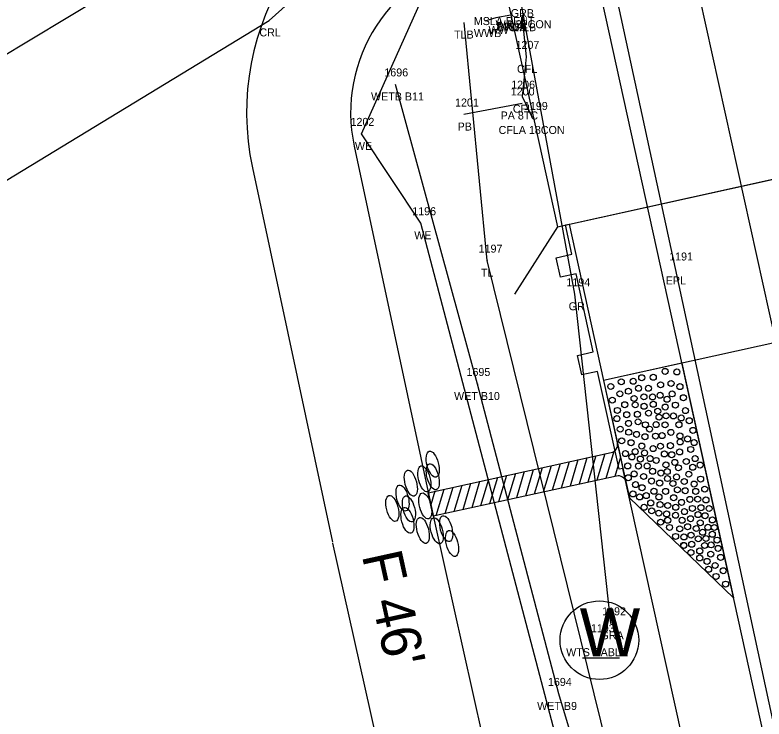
# Model space of a CAD drawing. Extents: x 2521558 to 2524785, y 882711 to 887632.
# Drawn here: x 2523713 to 2523806.5, y 884989.6 to 885077.6 of the extents above; entities that cross this region are included whole.
import ezdxf

# ---------------------------------------------------------------- set-up
doc = ezdxf.new("R2010")
doc.units = 0
for name, color, linetype in [('RD_EV_JW', 7, 'Continuous'), ('RD_EX_BldgApp_txCode', 7, 'Continuous'), ('RD_EX_Bridge', 7, 'Continuous'), ('RD_EX_Bridge_txCode', 7, 'Continuous'), ('RD_EX_Conc', 7, 'Continuous'), ('RD_EX_Conc_txCode', 7, 'Continuous'), ('RD_EX_DR_Pipe', 7, 'Continuous'), ('RD_EX_DR_Pipe_txCode', 7, 'Continuous'), ('RD_EX_GuardRail', 7, 'Continuous'), ('RD_EX_GuardRail_txCode', 7, 'Continuous'), ('RD_EX_H2O', 7, 'Continuous'), ('RD_EX_H2O_txCode', 7, 'Continuous'), ('RD_EX_H2O_WetLd_txCode', 7, 'Continuous'), ('RD_EX_Misc_txCode', 7, 'Continuous'), ('RD_EX_Road', 7, 'Continuous'), ('RD_EX_Road_txCode', 7, 'Continuous'), ('RD_EX_UT', 7, 'Continuous'), ('RD_EX_UT_txCode', 7, 'Continuous'), ('RD_EX_VEG', 7, 'Continuous'), ('RD_EX_VEG_txCode', 7, 'Continuous'), ('RD_HC_Cl', 7, 'Continuous'), ('RD_PD_Bridge', 7, 'Continuous'), ('RD_PD_CstnLmt', 7, 'Continuous'), ('RD_PD_DR_ErosCtrl', 7, 'Continuous'), ('RD_PD_Final_TrvlWay', 7, 'Continuous'), ('RD_PD_GR', 7, 'Continuous'), ('RD_PD_PaveShd', 7, 'Continuous'), ('RD_SMD_Locator', 7, 'Continuous')]:
    doc.layers.add(name, color=color, linetype=linetype)

# ---------------------------------------------------------------- blocks, each defined once
blk = doc.blocks.new('TBC1')
at = {"layer": 'RD_PD_GR'}
blk.add_lwpolyline([(12.5, 2.5), (15, 2.5), (15, 0.492), (25, 0.492), (25, 2.5), (27.5, 2.5), (27.5, 0.492), (31.25, 0.492), (31.25, 0), (0, 0), (0, 0.492), (12.5, 0.492)], close=True, dxfattribs=at)

msp = doc.modelspace()

# ---------------------------------------------------------------- linework, layer by layer
at = {"layer": 'RD_EV_JW'}
msp.add_lwpolyline([(2523827.748, 884469.643), (2523867.429, 884517.673), (2523885.95, 884534.838), (2523882.771, 884582.718), (2523847.739, 884736.424), (2523822.93, 884833.786), (2523804.257, 884914.891), (2523780.91, 884992.763), (2523770.735, 885031.476), (2523760.496, 885068.896)], dxfattribs=at)
at = {"layer": 'RD_EX_Bridge'}
msp.add_lwpolyline([(2523774.897, 885077.54), (2523773.018, 885077.212), (2523771.668, 885076.8)], dxfattribs=at)
at = {"layer": 'RD_EX_Conc'}
msp.add_lwpolyline([(2523777.605, 885064.707), (2523776.362, 885067.363), (2523776.876, 885072.337), (2523776.323, 885077.543)], dxfattribs=at)
at = {"layer": 'RD_EX_DR_Pipe'}
msp.add_line((2523776.322, 885066.515), (2523769.037, 885065.137), dxfattribs=at)
at = {"layer": 'RD_EX_GuardRail'}
msp.add_lwpolyline([(2523787.377, 885001.584), (2523782.908, 885042.685), (2523776.151, 885079.302)], dxfattribs=at)
at = {"layer": 'RD_EX_H2O'}
for points in [[(2523582.816, 884766.342), (2523598.112, 884856.984), (2523627.586, 884901.753), (2523623.762, 884928.278), (2523586.58, 884955.428), (2523600.942, 884974.118), (2523633.055, 884997.681), (2523679.166, 885037.048), (2523744.717, 885076.895), (2523769.376, 885098.995), (2523825.47, 885108.66), (2523825.47, 885108.66), (2523845.237, 885110.828), (2523890.252, 885154.934), (2523858.435, 885178.041), (2523850.814, 885196.928), (2523892.509, 885249.744), (2523936.89, 885290.086), (2523980.857, 885285.467), (2524009.058, 885269.77), (2524037.386, 885280.087)], [(2523792.732, 884941.121), (2523763.674, 885051.555), (2523756.264, 885062.719), (2523770.471, 885094.548), (2523817.567, 885105.706), (2523827.825, 885105.996)]]:
    msp.add_lwpolyline(points, dxfattribs=at)
at = {"layer": 'RD_EX_Road'}
for p, q in [((2523795.465, 885045.906), (2523788.047, 885080.306)), ((2523816.996, 884946.299), (2523795.465, 885045.906))]:
    msp.add_line(p, q, dxfattribs=at)
at = {"layer": 'RD_EX_UT'}
msp.add_line((2523783.84, 884997.269), (2523788.469, 884997.269), dxfattribs=at)
msp.add_circle((2523785.968, 884999.477), 4.908, dxfattribs=at)
at = {"layer": 'RD_EX_VEG'}
msp.add_lwpolyline([(2523800.231, 884418.22), (2523892.245, 884498.974), (2523844.575, 884752.813), (2523771.945, 885046.883), (2523769.056, 885076.621)], dxfattribs=at)
at = {"layer": 'RD_HC_Cl'}
for p, q in [((2523641.165, 885794.201), (2524197.759, 883266.557)), ((2523672.044, 885048.634), (2523837.18, 885148.323))]:
    msp.add_line(p, q, dxfattribs=at)
at = {"layer": 'RD_PD_Bridge'}
for p, q in [((2523780.729, 885051.128), (2523826.629, 885061.235)), ((2523782.194, 885051.45), (2523786.495, 885031.918)), ((2523780.729, 885051.128), (2523775.344, 885042.702)), ((2523829.465, 885041.381), (2523786.495, 885031.918))]:
    msp.add_line(p, q, dxfattribs=at)
for points in [[(2523752.772, 885178.086), (2523780.729, 885051.128)], [(2523780.729, 885051.128), (2523826.629, 885061.235)]]:
    msp.add_lwpolyline(points, dxfattribs=at)
at = {"layer": 'RD_PD_CstnLmt'}
for p, q in [((2523755.336, 885061.182), (2523765.326, 885014.455)), ((2523765.326, 885014.455), (2523787.173, 884916.87))]:
    msp.add_line(p, q, dxfattribs=at)
msp.add_arc((2523774.894, 885065.364), 20, 102.41848, 192.06773, dxfattribs=at)
at = {"layer": 'RD_PD_DR_ErosCtrl'}
for p, q in [((2523742.623, 885058.464), (2523752.613, 885011.737)), ((2523752.64, 885011.615), (2523774.487, 884914.03))]:
    msp.add_line(p, q, dxfattribs=at)
msp.add_arc((2523774.894, 885065.364), 33, 102.41848, 192.06773, dxfattribs=at)
at = {"layer": 'RD_PD_Final_TrvlWay'}
msp.add_line((2523718.306, 885388.085), (2523992.495, 884142.916), dxfattribs=at)
at = {"layer": 'RD_PD_GR'}
msp.add_line((2523896.44, 884532.63), (2523788.914, 885020.932), dxfattribs=at)
at = {"layer": 'RD_PD_PaveShd'}
for p, q in [((2523796.261, 885034.069), (2523786.495, 885031.918)), ((2523796.261, 885034.069), (2523802.712, 885004.771)), ((2523786.495, 885031.918), (2523788.43, 885023.129)), ((2523764.591, 885017.892), (2523787.453, 885022.914)), ((2523785.523, 885022.49), (2523784.539, 885019.203)), ((2523785.523, 885022.49), (2523784.539, 885019.203)), ((2523786.64, 885022.736), (2523785.656, 885019.448)), ((2523786.64, 885022.736), (2523785.656, 885019.448)), ((2523787.777, 885023.049), (2523786.773, 885019.693)), ((2523788.43, 885023.129), (2523789.076, 885020.199)), ((2523781.053, 885021.509), (2523780.069, 885018.221)), ((2523781.053, 885021.509), (2523780.069, 885018.221)), ((2523782.171, 885021.754), (2523781.187, 885018.466)), ((2523782.171, 885021.754), (2523781.187, 885018.466)), ((2523783.288, 885021.999), (2523782.304, 885018.712)), ((2523784.405, 885022.245), (2523783.421, 885018.957)), ((2523784.405, 885022.245), (2523783.421, 885018.957)), ((2523788.606, 885022.33), (2523787.89, 885019.939)), ((2523777.702, 885020.772), (2523776.718, 885017.485)), ((2523777.702, 885020.772), (2523776.718, 885017.485)), ((2523778.819, 885021.018), (2523777.835, 885017.73)), ((2523778.819, 885021.018), (2523777.835, 885017.73)), ((2523779.936, 885021.263), (2523778.952, 885017.975)), ((2523779.936, 885021.263), (2523778.952, 885017.975)), ((2523788.099, 885019.985), (2523765.218, 885014.959)), ((2523773.233, 885019.791), (2523772.249, 885016.503)), ((2523773.233, 885019.791), (2523772.37, 885016.908)), ((2523774.35, 885020.036), (2523773.366, 885016.748)), ((2523774.35, 885020.036), (2523773.366, 885016.748)), ((2523775.467, 885020.281), (2523774.483, 885016.994)), ((2523775.467, 885020.281), (2523774.483, 885016.994)), ((2523776.584, 885020.527), (2523775.6, 885017.239)), ((2523776.584, 885020.527), (2523775.6, 885017.239)), ((2523789.076, 885020.199), (2523789.721, 885017.269)), ((2523768.763, 885018.809), (2523767.779, 885015.521)), ((2523768.763, 885018.809), (2523767.779, 885015.521)), ((2523769.881, 885019.054), (2523768.897, 885015.767)), ((2523769.881, 885019.054), (2523768.897, 885015.767)), ((2523770.998, 885019.3), (2523770.014, 885016.012)), ((2523770.998, 885019.3), (2523770.014, 885016.012)), ((2523772.115, 885019.545), (2523771.131, 885016.258)), ((2523772.115, 885019.545), (2523771.131, 885016.258)), ((2523765.218, 885014.959), (2523764.591, 885017.892)), ((2523765.412, 885018.073), (2523764.91, 885016.398)), ((2523766.529, 885018.318), (2523765.545, 885015.03)), ((2523766.529, 885018.318), (2523765.666, 885015.436)), ((2523767.646, 885018.564), (2523766.662, 885015.276)), ((2523767.646, 885018.564), (2523766.662, 885015.276)), ((2523802.712, 885004.771), (2523789.721, 885017.269))]:
    msp.add_line(p, q, dxfattribs=at)
for centre in [(2523794.177, 885033.047), (2523794.177, 885033.047), (2523795.645, 885032.98), (2523795.645, 885032.98), (2523788.701, 885031.749), (2523788.701, 885031.749), (2523790.191, 885031.82), (2523790.191, 885031.82), (2523791.255, 885032.267), (2523791.255, 885032.267), (2523792.695, 885032.312), (2523792.695, 885032.312), (2523794.925, 885031.542), (2523794.925, 885031.542), (2523787.391, 885031.169), (2523787.391, 885031.169), (2523787.391, 885031.169), (2523789.59, 885030.574), (2523789.59, 885030.574), (2523790.857, 885030.939), (2523790.857, 885030.939), (2523792.098, 885030.94), (2523792.098, 885030.94), (2523793.614, 885031.376), (2523793.614, 885031.376), (2523796.028, 885031.15), (2523796.028, 885031.15), (2523788.522, 885030.252), (2523788.522, 885030.252), (2523790.297, 885029.666), (2523790.297, 885029.666), (2523791.529, 885029.869), (2523791.529, 885029.869), (2523792.61, 885029.863), (2523792.61, 885029.863), (2523793.554, 885030.07), (2523793.554, 885030.07), (2523794.424, 885029.569), (2523794.424, 885029.569), (2523795.053, 885030.242), (2523795.053, 885030.242), (2523796.459, 885029.76), (2523796.459, 885029.76), (2523787.581, 885029.458), (2523787.581, 885029.458), (2523789.128, 885028.892), (2523789.128, 885028.892), (2523790.445, 885028.871), (2523790.445, 885028.871), (2523791.55, 885028.688), (2523791.55, 885028.688), (2523792.699, 885028.941), (2523792.699, 885028.941), (2523794.188, 885028.599), (2523794.188, 885028.599), (2523795.46, 885028.839), (2523795.46, 885028.839), (2523788.21, 885028.175), (2523788.21, 885028.175), (2523790.717, 885027.693), (2523790.717, 885027.693), (2523792.104, 885027.837), (2523792.104, 885027.837), (2523793.26, 885028.082), (2523796.722, 885028.151), (2523796.722, 885028.151), (2523788.153, 885027.158), (2523788.153, 885027.158), (2523789.378, 885027.639), (2523789.378, 885027.639), (2523790.809, 885026.756), (2523790.809, 885026.756), (2523793.423, 885027.339), (2523793.423, 885027.339), (2523794.299, 885027.497), (2523794.299, 885027.497), (2523795.224, 885027.483), (2523795.224, 885027.483), (2523796.188, 885027.242), (2523796.188, 885027.242), (2523797.198, 885026.893), (2523797.198, 885026.893), (2523788.569, 885025.835), (2523788.569, 885025.835), (2523789.612, 885026.556), (2523789.612, 885026.556), (2523791.71, 885026.383), (2523791.71, 885026.383), (2523792.229, 885025.836), (2523792.229, 885025.836), (2523793.053, 885026.403), (2523793.053, 885026.403), (2523794.168, 885026.372), (2523794.168, 885026.372), (2523795.909, 885026.389), (2523795.909, 885026.389), (2523789.633, 885025.454), (2523789.633, 885025.454), (2523790.607, 885025.184), (2523790.607, 885025.184), (2523791.656, 885024.89), (2523791.656, 885024.89), (2523792.982, 885024.969), (2523792.982, 885024.969), (2523793.808, 885025.033), (2523793.808, 885025.033), (2523794.899, 885025.43), (2523794.899, 885025.43), (2523796.028, 885024.989), (2523796.028, 885024.989), (2523797.661, 885025.679), (2523797.661, 885025.679), (2523788.751, 885024.374), (2523788.751, 885024.374), (2523789.924, 885024.147), (2523789.924, 885024.147), (2523796.051, 885024.238), (2523796.051, 885024.238), (2523796.992, 885024.618), (2523796.992, 885024.618), (2523797.807, 885024.157), (2523790.438, 885023.028), (2523790.438, 885023.028), (2523791.266, 885023.725), (2523791.266, 885023.725), (2523792.68, 885023.406), (2523792.68, 885023.406), (2523793.598, 885023.71), (2523793.598, 885023.71), (2523794.837, 885023.774), (2523794.837, 885023.774), (2523795.989, 885022.995), (2523795.989, 885022.995), (2523797.383, 885023.302), (2523797.383, 885023.302), (2523789.226, 885022.785), (2523789.226, 885022.785), (2523790.029, 885022.359), (2523790.029, 885022.359), (2523791.09, 885022.103), (2523791.09, 885022.103), (2523791.609, 885022.864), (2523791.609, 885022.864), (2523792.304, 885022.154), (2523792.304, 885022.154), (2523794.092, 885022.736), (2523794.092, 885022.736), (2523795.002, 885022.647), (2523795.002, 885022.647), (2523797.929, 885022.157), (2523797.929, 885022.157), (2523789.509, 885021.243), (2523789.509, 885021.243), (2523790.85, 885021.234), (2523790.85, 885021.234), (2523791.928, 885021.243), (2523791.928, 885021.243), (2523793.064, 885021.927), (2523793.064, 885021.927), (2523794.284, 885021.376), (2523794.284, 885021.376), (2523795.39, 885021.686), (2523795.39, 885021.686), (2523796.828, 885021.793), (2523796.828, 885021.793), (2523798.556, 885021.349), (2523798.556, 885021.349), (2523790.304, 885020.24), (2523790.304, 885020.24), (2523792.616, 885020.572), (2523792.616, 885020.572), (2523793.648, 885020.356), (2523793.648, 885020.356), (2523794.447, 885020.541), (2523794.447, 885020.541), (2523795.849, 885021.011), (2523795.849, 885021.011), (2523797.14, 885020.211), (2523797.14, 885020.211), (2523797.624, 885021.069), (2523797.624, 885021.069), (2523789.581, 885019.774), (2523789.581, 885019.774), (2523791.492, 885019.926), (2523791.492, 885019.926), (2523792.478, 885019.352), (2523792.478, 885019.352), (2523794.474, 885019.665), (2523794.474, 885019.665), (2523795.609, 885019.863), (2523795.609, 885019.863), (2523796.576, 885019.295), (2523796.576, 885019.295), (2523798.61, 885019.596), (2523798.61, 885019.596), (2523790.483, 885018.905), (2523790.483, 885018.905), (2523791.298, 885018.516), (2523791.298, 885018.516), (2523793.498, 885019.099), (2523793.498, 885019.099), (2523795.158, 885019.047), (2523795.158, 885019.047), (2523797.805, 885018.979), (2523797.805, 885018.979), (2523799.125, 885018.346), (2523799.125, 885018.346), (2523790.156, 885017.741), (2523790.156, 885017.741), (2523790.156, 885017.741), (2523790.995, 885017.367), (2523790.995, 885017.367), (2523791.829, 885017.53), (2523791.829, 885017.53), (2523792.778, 885018.074), (2523792.778, 885018.074), (2523793.414, 885017.367), (2523793.414, 885017.367), (2523794.245, 885018.069), (2523794.245, 885018.069), (2523795.708, 885018.262), (2523795.708, 885018.262), (2523796.687, 885018.145), (2523796.687, 885018.145), (2523798.005, 885018.061), (2523798.005, 885018.061), (2523792.384, 885016.62), (2523792.384, 885016.62), (2523795.247, 885017.273), (2523795.247, 885017.273), (2523796.23, 885016.69), (2523796.23, 885016.69), (2523797.274, 885017.07), (2523797.274, 885017.07), (2523798.251, 885017.088), (2523798.251, 885017.088), (2523799.279, 885016.998), (2523799.279, 885016.998), (2523791.561, 885016.081), (2523791.561, 885016.081), (2523792.502, 885015.634), (2523792.502, 885015.634), (2523793.543, 885016.418), (2523793.543, 885016.418), (2523794.5, 885016.298), (2523794.5, 885016.298), (2523795.509, 885016.078), (2523795.509, 885016.078), (2523796.597, 885015.531), (2523796.597, 885015.531), (2523797.58, 885015.934), (2523797.58, 885015.934), (2523798.659, 885016.025), (2523798.659, 885016.025), (2523799.679, 885015.921), (2523799.679, 885015.921), (2523793.388, 885015.348), (2523793.388, 885015.348), (2523794.369, 885015.241), (2523794.369, 885015.241), (2523795.477, 885015.075), (2523795.477, 885015.075), (2523797.351, 885014.644), (2523797.351, 885014.644), (2523798.288, 885015.167), (2523798.288, 885015.167), (2523799.166, 885015.023), (2523799.166, 885015.023), (2523793.605, 885014.216), (2523793.616, 885014.214), (2523794.506, 885014.456), (2523794.506, 885014.456), (2523796.308, 885014.448), (2523796.308, 885014.448), (2523796.992, 885013.653), (2523796.992, 885013.653), (2523798.57, 885014.138), (2523798.57, 885014.138), (2523800.085, 885014.5), (2523800.085, 885014.5), (2523794.734, 885013.56), (2523794.734, 885013.56), (2523796.006, 885013.387), (2523796.006, 885013.387), (2523798.062, 885013.427), (2523798.062, 885013.427), (2523798.865, 885012.951), (2523798.865, 885012.951), (2523799.526, 885013.58), (2523799.526, 885013.58), (2523800.068, 885012.709), (2523800.068, 885012.709), (2523800.322, 885013.555), (2523800.322, 885013.555), (2523795.493, 885012.436), (2523795.493, 885012.436), (2523796.537, 885012.372), (2523796.537, 885012.372), (2523797.422, 885012.591), (2523797.422, 885012.591), (2523798.324, 885012.132), (2523798.324, 885012.132), (2523799.283, 885012.176), (2523799.283, 885012.176), (2523800.664, 885011.976), (2523800.664, 885011.976), (2523796.5, 885011.323), (2523796.524, 885011.299), (2523797.507, 885011.455), (2523797.507, 885011.455), (2523799.116, 885011.305), (2523799.116, 885011.305), (2523799.93, 885011.38), (2523799.93, 885011.38), (2523800.803, 885010.942), (2523800.803, 885010.942), (2523797.408, 885010.427), (2523797.408, 885010.427), (2523798.499, 885010.627), (2523798.499, 885010.627), (2523799.88, 885010.226), (2523799.88, 885010.226), (2523798.498, 885009.749), (2523799.421, 885009.323), (2523799.421, 885009.323), (2523801.117, 885009.82), (2523801.117, 885009.82), (2523799.609, 885008.334), (2523799.609, 885008.334), (2523800.425, 885008.81), (2523800.425, 885008.81), (2523801.434, 885008.154), (2523801.434, 885008.154), (2523800.546, 885007.439), (2523800.546, 885007.439), (2523801.736, 885006.481)]:
    msp.add_circle(centre, 0.375, dxfattribs=at)
for centre, start, end in [((2523787.239, 885023.891), 282.38886, 12.41848), ((2523788.314, 885019.008), 12.41848, 102.38886)]:
    msp.add_arc(centre, 1, start, end, dxfattribs=at)
for centre in [(2523765.147, 885021.461), (2523765.147, 885021.461), (2523765.154, 885019.888), (2523765.154, 885019.888), (2523762.41, 885019.094), (2523762.41, 885019.094), (2523764.099, 885019.623), (2523764.099, 885019.623), (2523761.376, 885017.232), (2523761.376, 885017.232), (2523764.219, 885016.245), (2523764.219, 885016.245), (2523760.099, 885015.939), (2523760.099, 885015.939), (2523762.17, 885015.878), (2523762.17, 885015.878), (2523761.988, 885014.444), (2523761.988, 885014.444), (2523766.828, 885013.409), (2523763.908, 885013.188), (2523763.908, 885013.188), (2523765.652, 885013.142), (2523765.652, 885013.142), (2523767.556, 885011.56)]:
    msp.add_ellipse(centre, major_axis=(0.426, -1.616), ratio=0.429445, dxfattribs=at)
at = {"layer": 'RD_SMD_Locator'}
for centre in [(2523744.717, 885076.895), (2523771.668, 885076.8), (2523773.018, 885077.212), (2523774.897, 885077.54), (2523776.323, 885077.543), (2523769.056, 885076.621), (2523776.876, 885072.337), (2523760.496, 885068.896), (2523776.362, 885067.363), (2523776.322, 885066.515), (2523769.037, 885065.137), (2523777.605, 885064.707), (2523756.264, 885062.719), (2523763.674, 885051.555), (2523771.945, 885046.883), (2523795.465, 885045.906), (2523782.908, 885042.685), (2523770.735, 885031.476), (2523775.333, 885013.358), (2523787.377, 885001.584), (2523780.91, 884992.763)]:
    msp.add_circle(centre, 0.001, dxfattribs=at)

# ---------------------------------------------------------------- block references
at = {"layer": 'RD_PD_Bridge', "rotation": 102.41848259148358}
msp.add_blockref('TBC1', (2523788.914, 885020.932), dxfattribs=at)

# ---------------------------------------------------------------- texts
at = {"layer": 'RD_EX_BldgApp_txCode'}
msp.add_text('WA 32CON', height=1, dxfattribs=at).set_placement((2523773, 885075.915))
at = {"layer": 'RD_EX_Bridge_txCode'}
for s, p in [('WWB', (2523770.29, 885074.8)), ('WW', (2523772.112, 885075.212)), ('BRCA', (2523773.166, 885075.596)), ('BRCB', (2523773.182, 885075.596)), ('WWA', (2523773.503, 885075.54))]:
    msp.add_text(s, height=1, dxfattribs=at).set_placement(p)
at = {"layer": 'RD_EX_Conc_txCode'}
for s, p in [('CFLB', (2523774.646, 885075.543)), ('1207', (2523775.491, 885073.337)), ('CFL', (2523775.672, 885070.337)), ('1206', (2523774.952, 885068.363)), ('1199', (2523776.542, 885065.707)), ('CFL', (2523775.157, 885065.363)), ('CFLA 18CON', (2523773.377, 885062.707))]:
    msp.add_text(s, height=1, dxfattribs=at).set_placement(p)
at = {"layer": 'RD_EX_DR_Pipe_txCode'}
for s, p in [('1200', (2523774.897, 885067.515)), ('1201', (2523767.935, 885066.137)), ('PA 8TC', (2523773.629, 885064.515)), ('PB', (2523768.257, 885063.137))]:
    msp.add_text(s, height=1, dxfattribs=at).set_placement(p)
at = {"layer": 'RD_EX_GuardRail_txCode'}
for s, p in [('GRB', (2523774.899, 885077.302)), ('1194', (2523781.845, 885043.685)), ('GR', (2523782.129, 885040.685)), ('1192', (2523786.314, 885002.584)), ('GRA', (2523786.109, 884999.584))]:
    msp.add_text(s, height=1, dxfattribs=at).set_placement(p)
at = {"layer": 'RD_EX_H2O_txCode'}
for s, p in [('CRL', (2523743.489, 885074.895)), ('1202', (2523754.878, 885063.719)), ('WE', (2523755.425, 885060.719)), ('1196', (2523762.587, 885052.555)), ('WE', (2523762.835, 885049.555))]:
    msp.add_text(s, height=1, dxfattribs=at).set_placement(p)
at = {"layer": 'RD_EX_H2O_WetLd_txCode'}
for s, p in [('1696', (2523759.102, 885069.896)), ('WETB B11', (2523757.44, 885066.896)), ('1695', (2523769.365, 885032.476)), ('WET B10', (2523767.813, 885029.476)), ('1694', (2523779.54, 884993.763)), ('WET B9', (2523778.193, 884990.763))]:
    msp.add_text(s, height=1, dxfattribs=at).set_placement(p)
at = {"layer": 'RD_EX_Misc_txCode'}
msp.add_text('MSLA BENT', height=1, dxfattribs=at).set_placement((2523770.279, 885076.307))
at = {"layer": 'RD_EX_Road_txCode'}
for s, p in [('1191', (2523794.686, 885046.906)), ('EPL', (2523794.261, 885043.906))]:
    msp.add_text(s, height=1, dxfattribs=at).set_placement(p)
at = {"layer": 'RD_EX_UT'}
msp.add_text('W', height=6, dxfattribs=at).set_placement((2523783.504, 884997.476))
at = {"layer": 'RD_EX_UT_txCode'}
for s, p in [('1193', (2523784.905, 885000.477)), ('WTS CABLE', (2523781.815, 884997.477))]:
    msp.add_text(s, height=1, dxfattribs=at).set_placement(p)
at = {"layer": 'RD_EX_VEG_txCode'}
for s, p in [('TLB', (2523767.812, 885074.621)), ('1197', (2523770.882, 885047.883)), ('TL', (2523771.173, 885044.883))]:
    msp.add_text(s, height=1, dxfattribs=at).set_placement(p)
at = {"layer": 'RD_PD_CstnLmt'}
msp.add_text("F 46'", height=5, rotation=282.41848, dxfattribs=at).set_placement((2523756.274, 885010.084))

doc.saveas('drawing.dxf')
